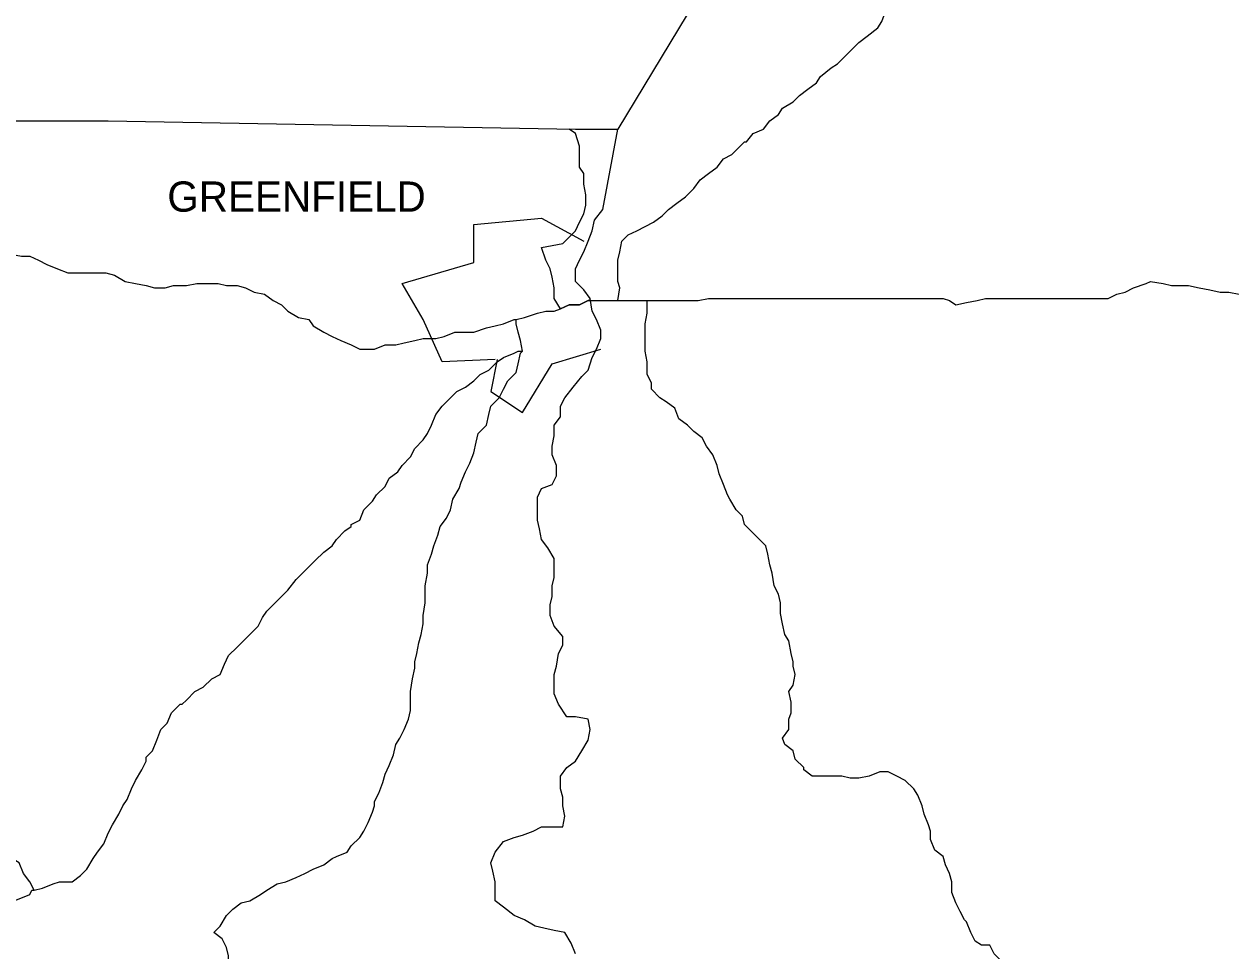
# Model space of a CAD drawing. Extents: x 0 to 34, y 0 to 22.
# Drawn here: x 4.361 to 5.139, y 18.753 to 19.351 of the extents above; entities that cross this region are included whole.
import ezdxf

# ---------------------------------------------------------------- set-up
doc = ezdxf.new("R2010")
doc.units = 0
doc.layers.add('Default', color=7, linetype='Continuous')

msp = doc.modelspace()

# ---------------------------------------------------------------- linework, layer by layer
at = {"layer": 'Default'}
for points in [[(5.12011, 19.9072), (5.08739, 19.85129), (4.99604, 19.69996), (4.74381, 19.28275)], [(4.82697, 19.27457), (4.83106, 19.28002), (4.83788, 19.28275), (4.84197, 19.2882), (4.84743, 19.29229), (4.85015, 19.29638), (4.85697, 19.30047), (4.86106, 19.30456), (4.86651, 19.30865), (4.87197, 19.31274), (4.87469, 19.31683), (4.88151, 19.32229), (4.8856, 19.32501), (4.89105, 19.33047), (4.89651, 19.33592), (4.89924, 19.33865), (4.90469, 19.34274), (4.91151, 19.34819), (4.91423, 19.35228), (4.9156, 19.35637), (4.91696, 19.35774)], [(3.97756, 19.29775), (4.13845, 19.29366), (4.33205, 19.2882), (4.41522, 19.2882), (4.71654, 19.28275), (4.74381, 19.28275)], [(4.71654, 18.75101), (4.71381, 18.75783), (4.70972, 18.76465), (4.7029, 18.76601), (4.69609, 18.76738), (4.69063, 18.76874), (4.68382, 18.77283), (4.677, 18.77556), (4.67018, 18.78101), (4.66473, 18.7851), (4.66473, 18.79192), (4.66473, 18.79737), (4.66336, 18.80419), (4.662, 18.80964), (4.66473, 18.81646), (4.67018, 18.82328), (4.677, 18.826), (4.68245, 18.82737), (4.68927, 18.83009), (4.69472, 18.83282), (4.70154, 18.83282), (4.70836, 18.83282), (4.70972, 18.83964), (4.70836, 18.84645), (4.70836, 18.85191), (4.70699, 18.85736), (4.70699, 18.86554), (4.71108, 18.871), (4.71654, 18.87509), (4.72063, 18.8819), (4.72472, 18.88872), (4.72608, 18.89554), (4.72472, 18.90235), (4.71654, 18.90372), (4.71108, 18.90372), (4.70563, 18.9119), (4.7029, 18.91871), (4.7029, 18.92417), (4.7029, 18.93099), (4.70427, 18.93644), (4.70563, 18.94462), (4.70836, 18.95007), (4.70836, 18.95553), (4.7029, 18.96234), (4.70018, 18.96916), (4.70018, 18.97598), (4.70154, 18.98143), (4.70154, 18.98825), (4.7029, 18.9937), (4.7029, 19.00052), (4.7029, 19.00597), (4.69881, 19.01279), (4.69472, 19.01824), (4.69336, 19.02506), (4.692, 19.03052), (4.692, 19.03733), (4.692, 19.04551), (4.69472, 19.05097), (4.70154, 19.05369), (4.70427, 19.05915), (4.70427, 19.06596), (4.70154, 19.07278), (4.70154, 19.07824), (4.7029, 19.08505), (4.7029, 19.09187), (4.70699, 19.09732), (4.70699, 19.10414), (4.70972, 19.10959), (4.71517, 19.11641), (4.72063, 19.12323), (4.72472, 19.12732), (4.72744, 19.1355), (4.73017, 19.14095), (4.7329, 19.14777), (4.7329, 19.15322), (4.73017, 19.16004), (4.72744, 19.16549), (4.72608, 19.17367), (4.72199, 19.17913), (4.71654, 19.18458), (4.71654, 19.19276), (4.71926, 19.19822), (4.72199, 19.20367), (4.72472, 19.21049), (4.72744, 19.2173), (4.72881, 19.22412), (4.73426, 19.23094), (4.74381, 19.28275)], [(4.70699, 19.16686), (4.7029, 19.17367), (4.7029, 19.18049), (4.70154, 19.18731), (4.70018, 19.19276), (4.69745, 19.19822), (4.69472, 19.2064), (4.70154, 19.20776), (4.70836, 19.20912), (4.71245, 19.21321), (4.71654, 19.2173), (4.71926, 19.22276), (4.72199, 19.22821), (4.72335, 19.23367), (4.72335, 19.24048), (4.72199, 19.2473), (4.72199, 19.25412), (4.71926, 19.25821), (4.71926, 19.26639), (4.71926, 19.27184), (4.71654, 19.28002), (4.71245, 19.28275)], [(4.79289, 19.24457), (4.79698, 19.25003), (4.80243, 19.25412), (4.80789, 19.25821), (4.81198, 19.26366), (4.81743, 19.26639), (4.82152, 19.27048), (4.82561, 19.27457), (4.82697, 19.27457)], [(4.74381, 19.17231), (4.74517, 19.18049), (4.74381, 19.18458), (4.74381, 19.19276), (4.74381, 19.19822), (4.74517, 19.20367), (4.74653, 19.21049), (4.75062, 19.21458), (4.75608, 19.2173), (4.76153, 19.22003), (4.76698, 19.22276), (4.77244, 19.22685), (4.77653, 19.23094), (4.78198, 19.23503), (4.78744, 19.23912), (4.79289, 19.24457), (4.79289, 19.24457)], [(4.66473, 19.13414), (4.63064, 19.13277), (4.61837, 19.16004), (4.60474, 19.18322), (4.65109, 19.19685), (4.65109, 19.22139), (4.69472, 19.22548), (4.72199, 19.21049)], [(4.34023, 19.20231), (4.34569, 19.20231), (4.35114, 19.20231), (4.35932, 19.20094), (4.36477, 19.20094), (4.37023, 19.19822), (4.37568, 19.19549), (4.3825, 19.19276), (4.38932, 19.19004), (4.39477, 19.19004), (4.40022, 19.19004), (4.40704, 19.19004), (4.41386, 19.19004), (4.41931, 19.18867), (4.42613, 19.18458), (4.43295, 19.18322), (4.43976, 19.18186), (4.44522, 19.18049), (4.45203, 19.18049), (4.45749, 19.18186), (4.45885, 19.18186)], [(4.45885, 19.18186), (4.46567, 19.18186), (4.47248, 19.18322), (4.4793, 19.18322), (4.48612, 19.18322), (4.49157, 19.18186), (4.49839, 19.18186), (4.50384, 19.18049), (4.5093, 19.17776), (4.51611, 19.1764), (4.52157, 19.17231), (4.52702, 19.16958), (4.53111, 19.16549), (4.53793, 19.1614), (4.54475, 19.16004), (4.54747, 19.15595), (4.55429, 19.15186), (4.55974, 19.14913), (4.5652, 19.14641), (4.57201, 19.14368), (4.57747, 19.14095), (4.5802, 19.14095), (4.5802, 19.14095)], [(4.76289, 19.17231), (4.76835, 19.17231), (4.77653, 19.17231), (4.78334, 19.17231), (4.79016, 19.17231), (4.79562, 19.17231), (4.80243, 19.17367), (4.80789, 19.17367), (4.8147, 19.17367), (4.82152, 19.17367), (4.82834, 19.17367), (4.83515, 19.17367), (4.84197, 19.17367), (4.84743, 19.17367), (4.85561, 19.17367), (4.86106, 19.17367), (4.86651, 19.17367), (4.87333, 19.17367), (4.88015, 19.17367), (4.88696, 19.17367), (4.89378, 19.17367), (4.89924, 19.17367), (4.90605, 19.17367), (4.91287, 19.17367), (4.91969, 19.17367), (4.9265, 19.17367), (4.93196, 19.17367), (4.94014, 19.17367), (4.94559, 19.17367), (4.95377, 19.17367), (4.95786, 19.17231), (4.96195, 19.16958), (4.96877, 19.17095), (4.97559, 19.17231), (4.98104, 19.17367), (4.98786, 19.17367), (4.99467, 19.17367), (5.00149, 19.17367), (5.00831, 19.17367), (5.01376, 19.17367), (5.02058, 19.17367), (5.0274, 19.17367), (5.03285, 19.17367), (5.04103, 19.17367), (5.04648, 19.17367), (5.0533, 19.17367), (5.06012, 19.17367), (5.06557, 19.1764), (5.07103, 19.17776), (5.07648, 19.18049), (5.08466, 19.18322), (5.08739, 19.18458), (5.09557, 19.18322), (5.10102, 19.18186), (5.1092, 19.18186), (5.11193, 19.18186), (5.11193, 19.18186)], [(5.11193, 19.18186), (5.11875, 19.18049), (5.12556, 19.17913), (5.13238, 19.17776), (5.13783, 19.17776), (5.14465, 19.1764)], [(4.67836, 19.16004), (4.68382, 19.1614), (4.692, 19.16413), (4.69745, 19.16549), (4.7029, 19.16549), (4.70699, 19.16686)], [(4.67836, 19.16004), (4.68382, 19.1614), (4.692, 19.16413), (4.69745, 19.16549), (4.7029, 19.16549), (4.70699, 19.16686)], [(4.72608, 19.17231), (4.72472, 19.17231), (4.71926, 19.16958), (4.71245, 19.16958), (4.70699, 19.16686)], [(4.70699, 19.16686), (4.71245, 19.16958), (4.71926, 19.16958), (4.72472, 19.17231), (4.72608, 19.17231)], [(4.70699, 19.16686), (4.71245, 19.16958), (4.71926, 19.16958), (4.72472, 19.17231), (4.72608, 19.17231)], [(4.72608, 19.17231), (4.7329, 19.17231), (4.73835, 19.17231), (4.74381, 19.17231), (4.74381, 19.17231)], [(4.74381, 19.17231), (4.75062, 19.17231), (4.75744, 19.17231), (4.76289, 19.17231), (4.76289, 19.17231)], [(4.8147, 19.04688), (4.81198, 19.05369), (4.80925, 19.06051), (4.80789, 19.06596), (4.80516, 19.07278), (4.80107, 19.07824), (4.79834, 19.08369), (4.79289, 19.08778), (4.7888, 19.09187), (4.78334, 19.09596), (4.78062, 19.10278), (4.77516, 19.10687), (4.77107, 19.10959), (4.76562, 19.11505), (4.76562, 19.11914), (4.76289, 19.12459), (4.76289, 19.13277), (4.76153, 19.13959), (4.76153, 19.14504), (4.76153, 19.15186), (4.76153, 19.15731), (4.76289, 19.16413), (4.76289, 19.16958), (4.76289, 19.17231)], [(4.5802, 19.14095), (4.58701, 19.14095), (4.59383, 19.14368), (4.60065, 19.14368), (4.6061, 19.14504), (4.61292, 19.14641), (4.61837, 19.14777), (4.62655, 19.14777), (4.63201, 19.14913), (4.63882, 19.15186), (4.64564, 19.15186), (4.65109, 19.15186), (4.65927, 19.15459), (4.66473, 19.15595), (4.67018, 19.15731), (4.677, 19.16004), (4.67836, 19.16004)], [(4.68245, 19.13959), (4.68109, 19.14641), (4.67972, 19.15186), (4.67836, 19.15731), (4.67836, 19.16004)], [(4.57201, 19.02779), (4.57747, 19.03052), (4.5802, 19.03733), (4.58565, 19.04279), (4.58838, 19.04688), (4.59383, 19.05233), (4.59656, 19.05778), (4.60201, 19.06187), (4.60474, 19.06596), (4.61019, 19.07142), (4.61292, 19.07687), (4.61837, 19.08233), (4.6211, 19.08642), (4.62382, 19.09187), (4.62655, 19.09869), (4.63064, 19.10414), (4.63473, 19.10823), (4.64019, 19.11368), (4.64564, 19.11641), (4.65109, 19.1205), (4.65518, 19.12459), (4.66064, 19.12732), (4.66609, 19.13277), (4.67018, 19.1355), (4.677, 19.13823), (4.67972, 19.13959), (4.68245, 19.13959)], [(4.61292, 18.93917), (4.61428, 18.94462), (4.61564, 18.95144), (4.61701, 18.95689), (4.61837, 18.96371), (4.61837, 18.96916), (4.61973, 18.97734), (4.61973, 18.98143), (4.61973, 18.98825), (4.6211, 18.99643), (4.6211, 19.00188), (4.62382, 19.0087), (4.62519, 19.01415), (4.62791, 19.02097), (4.62928, 19.02643), (4.63337, 19.03188), (4.6361, 19.03733), (4.63746, 19.04415), (4.64155, 19.05097), (4.64291, 19.05506), (4.64564, 19.06187), (4.64837, 19.06733), (4.65109, 19.07414), (4.65246, 19.08096), (4.65382, 19.08642), (4.65927, 19.09187), (4.66064, 19.09869), (4.662, 19.10414), (4.66745, 19.10959), (4.67018, 19.11505), (4.67291, 19.1205), (4.67836, 19.12595), (4.67972, 19.13141), (4.68109, 19.13823), (4.68245, 19.13959)], [(4.66609, 19.13414), (4.662, 19.11368), (4.68245, 19.10005), (4.70154, 19.13141), (4.7329, 19.14095)], [(4.85697, 18.93917), (4.85561, 18.94462), (4.85424, 18.9528), (4.85152, 18.95689), (4.85015, 18.96371), (4.84879, 18.97052), (4.84879, 18.97734), (4.84743, 18.9828), (4.8447, 18.98825), (4.84334, 18.99643), (4.84197, 19.00188), (4.84061, 19.0087), (4.83924, 19.01415), (4.83515, 19.01824), (4.83106, 19.02233), (4.82561, 19.02779), (4.82425, 19.03324), (4.82016, 19.03733), (4.81607, 19.04415), (4.8147, 19.04688)], [(4.46294, 18.9119), (4.46567, 18.91462), (4.47112, 18.92008), (4.47658, 18.92281), (4.48203, 18.92826), (4.48748, 18.93099), (4.49021, 18.9378), (4.49294, 18.94326), (4.49839, 18.94871), (4.50248, 18.9528), (4.50657, 18.95689), (4.51202, 18.96234), (4.51475, 18.9678), (4.51748, 18.97189), (4.52293, 18.97734), (4.52702, 18.98143), (4.53111, 18.98552), (4.53657, 18.99234), (4.54066, 18.99643), (4.54475, 19.00052), (4.54884, 19.00461), (4.55429, 19.01006), (4.55974, 19.01415), (4.56247, 19.01824), (4.56792, 19.0237), (4.57201, 19.02643), (4.57201, 19.02779)], [(4.58701, 18.84918), (4.58974, 18.85463), (4.59247, 18.86145), (4.59383, 18.8669), (4.59656, 18.87236), (4.59928, 18.87918), (4.60065, 18.88599), (4.60337, 18.89008), (4.6061, 18.89554), (4.60883, 18.90235), (4.61019, 18.90781), (4.61019, 18.91462), (4.61019, 18.92008), (4.61155, 18.92826), (4.61292, 18.93508), (4.61292, 18.93917)], [(4.86379, 18.871), (4.85833, 18.87645), (4.85697, 18.8819), (4.85152, 18.88599), (4.85015, 18.89008), (4.85424, 18.89554), (4.85424, 18.90235), (4.85561, 18.90644), (4.85561, 18.91326), (4.85424, 18.92008), (4.85697, 18.92417), (4.85833, 18.93099), (4.85697, 18.93644), (4.85697, 18.9378), (4.85697, 18.93917)], [(4.43976, 18.87781), (4.44385, 18.8819), (4.44658, 18.88872), (4.44931, 18.89554), (4.4534, 18.89963), (4.45612, 18.90644), (4.46158, 18.9119), (4.46294, 18.9119)], [(4.3675, 18.79192), (4.37296, 18.79328), (4.37977, 18.79601), (4.38386, 18.79737), (4.39204, 18.79737), (4.3975, 18.80146), (4.40159, 18.80555), (4.40568, 18.81237), (4.4084, 18.81646), (4.41249, 18.82191), (4.41522, 18.82873), (4.41795, 18.83418), (4.42204, 18.841), (4.42477, 18.84645), (4.42749, 18.85054), (4.43022, 18.85736), (4.43295, 18.86281), (4.43704, 18.86963), (4.43976, 18.87509), (4.43976, 18.87781)], [(4.3675, 18.79192), (4.36477, 18.79737), (4.36068, 18.80282), (4.35796, 18.80964), (4.35114, 18.81373), (4.34978, 18.81646), (4.34841, 18.82191), (4.3416, 18.82464), (4.33614, 18.82737), (4.33205, 18.83282), (4.3266, 18.83555), (4.32115, 18.83827), (4.31569, 18.841), (4.31024, 18.84509), (4.30615, 18.85054), (4.30206, 18.85463), (4.29797, 18.86009), (4.29251, 18.86554), (4.29115, 18.86963), (4.2857, 18.87509), (4.28433, 18.87509), (4.28433, 18.87509)], [(4.96741, 18.77283), (4.96468, 18.77828), (4.96195, 18.78374), (4.95923, 18.79055), (4.95923, 18.79737), (4.95786, 18.80282), (4.95514, 18.80828), (4.95377, 18.81373), (4.94832, 18.81782), (4.94559, 18.82464), (4.94559, 18.83009), (4.94423, 18.83418), (4.9415, 18.841), (4.94014, 18.84645), (4.93741, 18.85327), (4.93468, 18.85736), (4.92923, 18.86281), (4.92378, 18.86554), (4.91832, 18.86827), (4.91287, 18.86827), (4.90605, 18.86554), (4.89924, 18.86418), (4.89378, 18.86418), (4.88833, 18.86554), (4.88151, 18.86554), (4.87469, 18.86554), (4.86924, 18.86554), (4.86379, 18.86963), (4.86379, 18.871), (4.86379, 18.871)], [(4.56247, 18.81373), (4.56929, 18.81646), (4.57201, 18.82055), (4.57747, 18.826), (4.5802, 18.83009), (4.58292, 18.83555), (4.58565, 18.84236), (4.58701, 18.84645), (4.58701, 18.84918)], [(4.48339, 18.76465), (4.48748, 18.76874), (4.49157, 18.77556), (4.49566, 18.77965), (4.50112, 18.78374), (4.50657, 18.7851), (4.51339, 18.78919), (4.51748, 18.79192), (4.52429, 18.79601), (4.52975, 18.79737), (4.53657, 18.8001), (4.54202, 18.80282), (4.54747, 18.80555), (4.55429, 18.80828), (4.55974, 18.81237), (4.56247, 18.81373)], [(4.28161, 18.78919), (4.28706, 18.79192), (4.29251, 18.79192), (4.29933, 18.78919), (4.30615, 18.78783), (4.31024, 18.78374), (4.31569, 18.77965), (4.32115, 18.77828), (4.3266, 18.78101), (4.33342, 18.78101), (4.34023, 18.78237), (4.34705, 18.78237), (4.35114, 18.78374), (4.35796, 18.78646), (4.36477, 18.78919), (4.36614, 18.79192), (4.3675, 18.79192)], [(5.04648, 18.70602), (5.04239, 18.70602), (5.03558, 18.70875), (5.03012, 18.71011), (5.0274, 18.71557), (5.02331, 18.72102), (5.01922, 18.72375), (5.01376, 18.7292), (5.0124, 18.73465), (5.00695, 18.73874), (5.00286, 18.74147), (4.99604, 18.7442), (4.99058, 18.74692), (4.98649, 18.75101), (4.98377, 18.75647), (4.97831, 18.75647), (4.97422, 18.75919), (4.9715, 18.76465), (4.96877, 18.77147), (4.96741, 18.77283), (4.96741, 18.77283)], [(4.50521, 18.68557), (4.50384, 18.69239), (4.50248, 18.6992), (4.50112, 18.70466), (4.49839, 18.71011), (4.49839, 18.71693), (4.49703, 18.72375), (4.49566, 18.73056), (4.49566, 18.73602), (4.49294, 18.74283), (4.49294, 18.74965), (4.49157, 18.7551), (4.48885, 18.76056), (4.48339, 18.76465)]]:
    msp.add_lwpolyline(points, dxfattribs=at)

# ---------------------------------------------------------------- texts
msp.add_text('GREENFIELD', height=0.019502, dxfattribs=at).set_placement((4.4534, 19.22957))

doc.saveas('drawing.dxf')
